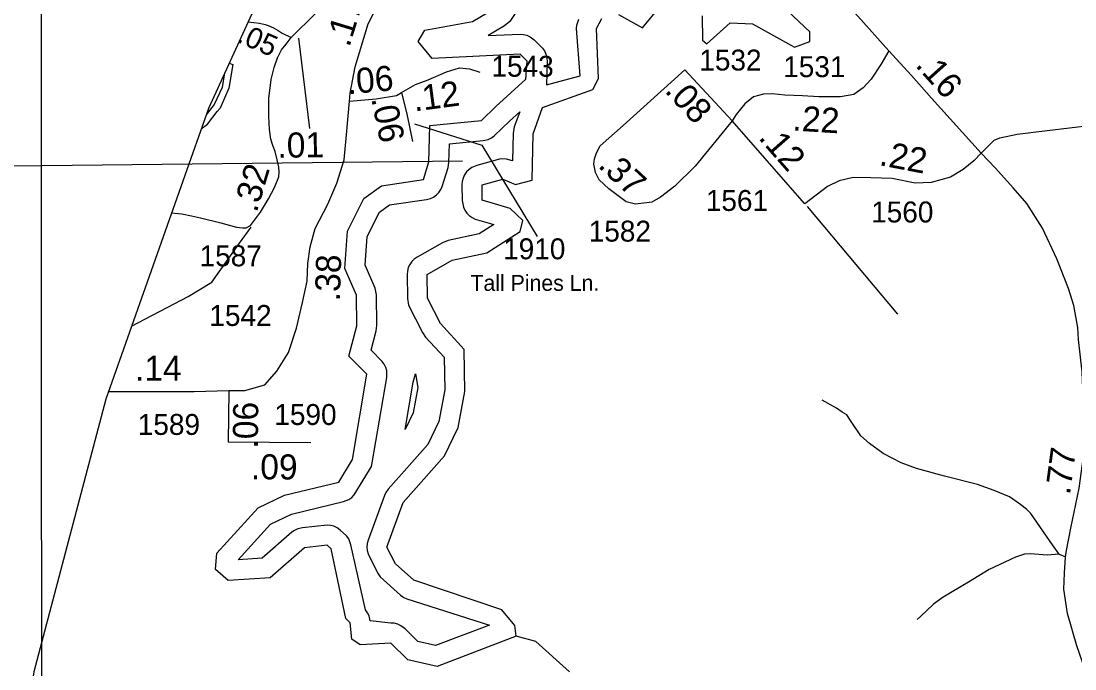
# Model space of a CAD drawing. Extents: x 2290615 to 2522933, y 819489 to 1012715.
# Drawn here: x 2321678 to 2327975, y 999420 to 1003289 of the extents above; entities that cross this region are included whole.
import ezdxf

# ---------------------------------------------------------------- set-up
doc = ezdxf.new("R2010")
doc.units = 0
for name, color, linetype in [('Exist Boundary Political CountyLine', 7, 'Continuous'), ('Exist Hydrographic Buffer Line', 7, 'Continuous'), ('Exist Hydrographic Creek Single Shore', 7, 'Continuous'), ('Exist Hydrographic Lake Shore', 7, 'Continuous'), ('Exist Road Non-System Type 51', 7, 'Continuous'), ('Exist Road Secondary Mileage Tenths English Label', 7, 'Continuous'), ('Exist Road Secondary Type 51 Attributed', 7, 'Continuous'), ('Exist Road Secondary Type 51 Label', 7, 'Continuous'), ('Exist Road Secondary Type 51 Number Label', 7, 'Continuous'), ('Map Preparation Inset Cut Line', 7, 'Continuous'), ('Map Preparation Longitude Latitude Lines', 7, 'Continuous')]:
    doc.layers.add(name, color=color, linetype=linetype)

msp = doc.modelspace()

# ---------------------------------------------------------------- linework, layer by layer
at = {"layer": 'Exist Boundary Political CountyLine'}
msp.add_lwpolyline([(2323478.1, 1004252.3), (2322797.9, 1002767.9), (2322184.3, 1001030.3), (2321753.9, 999403.1), (2320741.4, 993201.9), (2320116, 981859.9), (2320039, 981847.1), (2319958.9, 981832.4), (2319871.3, 981814.3), (2319737.2, 981784.5), (2319631.4, 981753.5), (2319582.3, 981738.9), (2319462.8, 981696.8)], dxfattribs=at)
at = {"layer": 'Exist Hydrographic Buffer Line'}
for points in [[(2324705.6, 1003451.2), (2324598.8, 1003287.4), (2324567.8, 1003261.1), (2324468.6, 1003202.8), (2324659.7, 1003211.8), (2324680.6, 1003209.9), (2324700.7, 1003204.5), (2324719.8, 1003195.7), (2324743.5, 1003177.7), (2324793.8, 1003128), (2324805.7, 1003110.9), (2324814.5, 1003091.9), (2324820, 1003071.7), (2324821.5, 1003043.2), (2324817.8, 1002908.1), (2324982, 1002951.9), (2325019.3, 1002961.8), (2324996.8, 1003245.2), (2324998.4, 1003266)], [(2324998.4, 1003266), (2325010.7, 1003301.4)], [(2322894.8, 1002979.5), (2322879.1, 1002893.5), (2322832, 1002791.2), (2322784.3, 1002729.5)], [(2324154.6, 999559.2), (2324048.8, 999582.6), (2323972.6, 999658.7), (2323947.7, 999677.8), (2323928.9, 999686.6), (2323908.6, 999692.1), (2323887.9, 999693.8), (2323764.4, 999706.1), (2323757.7, 999736.3), (2323748.8, 999755.1), (2323736.7, 999772.2), (2323649.4, 1000161.4), (2323635.9, 1000197), (2323623.8, 1000214.1), (2323585.8, 1000249.2), (2323566.8, 1000262.8), (2323547.9, 1000271.6), (2323527.6, 1000277.1), (2323506.9, 1000278.8), (2323359.2, 1000262.8), (2323331.8, 1000256.3), (2323312.9, 1000247.4), (2323295.7, 1000235.5), (2323118.5, 1000081.3), (2322974.6, 1000071.6), (2323168.5, 1000283.4), (2323293.6, 1000343.3), (2323605.3, 1000419.4), (2323636.9, 1000432), (2323654.1, 1000444), (2323668.9, 1000458.9), (2323761.3, 1000608.3), (2323771.6, 1000629.6), (2323777.1, 1000649.9), (2323863.1, 1001159.7), (2323864.9, 1001179.7), (2323863.1, 1001200.5), (2323857.5, 1001220.8), (2323848.9, 1001239.7), (2323836.8, 1001256.8), (2323769.5, 1001323.7), (2323799.9, 1001438.9), (2323803.8, 1001470.7), (2323801.7, 1001654.4), (2323794.6, 1001694.1), (2323735.3, 1001832.2), (2323746, 1002002.9), (2323819.6, 1002149), (2323879, 1002191.5), (2324100.1, 1002223.8), (2324123.9, 1002229.8), (2324142.7, 1002238.6), (2324160, 1002250.6), (2324174.7, 1002265.5), (2324186.8, 1002282.6), (2324195.4, 1002301.5), (2324229.7, 1002414.4), (2324234.8, 1002445.7), (2324237.7, 1002556.3), (2324440.1, 1002575.6), (2324469.8, 1002582.3), (2324488.9, 1002591.1), (2324506.1, 1002603.1), (2324597.8, 1002692.5), (2324657.8, 1002746.8), (2324625, 1002656.8), (2324617.8, 1002618), (2324615, 1002455.4), (2324578.5, 1002464), (2324557.8, 1002465.8), (2324537.1, 1002464), (2324400.7, 1002426.7), (2324372.8, 1002415.1), (2324355.6, 1002403.1), (2324340.8, 1002388.2), (2324328.7, 1002371.1), (2324320.1, 1002352.1), (2324314.6, 1002331.9), (2324312.7, 1002311.1), (2324313.8, 1002217.9), (2324321.1, 1002178.1), (2324329.8, 1002159.1), (2324341.8, 1002142), (2324356.6, 1002127.3), (2324373.8, 1002115.3), (2324392.7, 1002106.4), (2324503.6, 1002073.7), (2324415.5, 1002018), (2324229.5, 1001977.9), (2324195.6, 1001965), (2324045.5, 1001880), (2324027.5, 1001867.5), (2324012.7, 1001852.7), (2324000.8, 1001835.6), (2323992, 1001816.6), (2323986.5, 1001796.4), (2323984.9, 1001775.6), (2323986.7, 1001632.8), (2323994.1, 1001593.4), (2324076.7, 1001429)], [(2324076.7, 1001429), (2324095.6, 1001402.1), (2324207.3, 1001281), (2324209.6, 1001086.1), (2324174.7, 1000898.5), (2324108.1, 1000760.4), (2323871.9, 1000493.5), (2323857.7, 1000473.9), (2323849.1, 1000455.1), (2323752.1, 1000188.4), (2323746.6, 1000168.2)], [(2323973.2, 1000849.9), (2324020.7, 1001133.1), (2324035.3, 1001181.6), (2324049.6, 1001099.9), (2324021.4, 1000948.8), (2323973.2, 1000849.9)], [(2323746.6, 1000168.2), (2323744.7, 1000147.4), (2323746.6, 1000126.6), (2323752.1, 1000106.3), (2323809.1, 999993.1), (2323823.9, 999970.6), (2323944.9, 999860.9), (2323964.8, 999846.6), (2323983.8, 999837.8), (2324476.4, 999681.8), (2324154.6, 999559.2)]]:
    msp.add_lwpolyline(points, dxfattribs=at)
at = {"layer": 'Exist Hydrographic Creek Single Shore'}
msp.add_lwpolyline([(2324955.8, 999401.2), (2324753.8, 999583.3), (2324636.9, 999614.6)], dxfattribs=at)
at = {"layer": 'Exist Hydrographic Lake Shore'}
for points in [[(2325748.7, 1003320.6), (2325750.8, 1003176.1), (2325775.8, 1003154.3), (2325915.8, 1003278.2), (2326048.7, 1003273.8), (2326300.7, 1003133.2), (2326391.8, 1003166.6), (2326390.7, 1003225.6), (2326121.7, 1003480.3)], [(2325248.8, 1003329.5), (2325390.7, 1003250), (2325497.7, 1003375.8)], [(2324515.5, 1002779.8), (2324694.7, 1002942.2), (2324701.7, 1003050.9), (2324659.7, 1003091.7), (2324134.7, 1003066.9), (2324050.7, 1003168.5), (2324091.7, 1003235.8), (2324374.9, 1003286.7), (2324506.7, 1003364.5)], [(2324794.8, 1002772.4), (2325094.8, 1002880), (2325127.8, 1002947.1), (2325116.7, 1003245.2), (2325148.7, 1003305.6)], [(2322921.7, 1003038.2), (2322943.8, 1003031), (2322920.8, 1002888.7), (2322868.8, 1002769.8)], [(2322754.5, 1002645.1), (2322792.1, 1002674.4), (2322849.7, 1002749), (2322868.8, 1002769.8)], [(2322840.9, 1000013.3), (2322848.9, 1000112), (2323095.7, 1000381.5), (2323252.8, 1000457), (2323576.8, 1000536), (2323658.8, 1000670.7), (2323744.7, 1001179.7), (2323635.9, 1001286.9), (2323683.8, 1001469.4), (2323681.8, 1001653.1), (2323613.7, 1001811.1), (2323627.9, 1002035), (2323725.9, 1002229.4), (2323832.7, 1002306), (2324082.9, 1002342.6), (2324114.9, 1002449), (2324120.8, 1002665.7), (2324428.8, 1002695.1), (2324515.5, 1002779.8)], [(2324636.9, 999614.6), (2324627.9, 999679.9), (2324551.8, 999771.9), (2324024.8, 999950.4), (2323915.8, 1000047.7), (2323864.9, 1000147.4), (2323961.9, 1000413.9), (2324208.8, 1000693.2), (2324289.8, 1000860.8), (2324329.8, 1001075.8), (2324326.9, 1001328.5), (2324183.8, 1001483.5), (2324106.9, 1001634.5), (2324104.8, 1001775.6), (2324254.7, 1001860.6), (2324461.8, 1001905.2), (2324660.7, 1002031.6), (2324676.7, 1002097.8), (2324600.8, 1002170.2), (2324433.7, 1002219.2), (2324432.7, 1002311.1), (2324557.8, 1002345.7), (2324632.8, 1002312.7), (2324732.9, 1002339.8), (2324737.8, 1002615.8), (2324794.8, 1002772.4)], [(2324636.9, 999614.6), (2324163.9, 999434.2), (2323988.7, 999473), (2323887.9, 999573.8), (2323703.9, 999563), (2323653.9, 999597), (2323644.9, 999695.1), (2323618.8, 999720.4), (2323531.9, 1000136.9), (2323506.9, 1000158.9), (2323372.8, 1000143.5), (2323166.9, 999964.3), (2322916.7, 999947.5), (2322840.9, 1000013.3)]]:
    msp.add_lwpolyline(points, dxfattribs=at)
at = {"layer": 'Exist Road Non-System Type 51'}
for p, q in [((2326375, 1002182.6), (2326915.8, 1001538.5)), ((2326375, 1002182.6), (2326915.8, 1001538.5)), ((2327880.9, 1000105.4), (2327919.2, 1000090)), ((2327880.9, 1000105.4), (2327919.2, 1000090))]:
    msp.add_line(p, q, dxfattribs=at)
for points in [[(2327414.5, 1002499.6), (2327454, 1002537.7), (2327493.4, 1002578.7), (2327525.9, 1002592.7), (2327629.7, 1002614.4), (2327809.5, 1002636.1), (2328076, 1002668.7), (2328248, 1002705.9), (2328290.1, 1002715)], [(2322338.5, 1001466.9), (2322676.7, 1001643.7), (2322818, 1001729.7), (2322983.9, 1001963.4), (2323052.7, 1002057.8)], [(2327880.9, 1000105.4), (2327840.9, 1000161.6), (2327712.3, 1000347.7), (2327685.9, 1000374.4), (2327651.7, 1000400.6), (2327624.2, 1000419), (2327585.2, 1000447), (2327493.8, 1000485.7), (2327393.1, 1000521.4), (2327196.3, 1000571), (2327028.9, 1000617.5), (2326937.5, 1000650.1), (2326830.6, 1000705.9), (2326748.4, 1000766.4), (2326696.6, 1000812.3), (2326639.3, 1000897.6), (2326612.9, 1000936.4), (2326585, 1000953.4), (2326550.9, 1000976.7), (2326464.2, 1001024.8)], [(2327880.9, 1000105.4), (2327810.4, 1000098.6), (2327708.1, 1000106.4), (2327674, 1000104.8), (2327621.3, 1000087.8), (2327463.3, 1000013.3), (2327339.3, 999937.4), (2327189, 999847.4), (2327130.1, 999807.1), (2327052.6, 999732.7), (2327032.5, 999714.1)]]:
    msp.add_lwpolyline(points, dxfattribs=at)
at = {"layer": 'Exist Road Secondary Mileage Tenths English Label'}
msp.add_line((2323335.6, 1003186.9), (2323401.7, 1002647.3), dxfattribs=at)
at = {"layer": 'Exist Road Secondary Type 51 Attributed'}
for points in [[(2326864.1, 1003112.6), (2326678.5, 1003319.5), (2326521.6, 1003493), (2326437.5, 1003586.8), (2326392, 1003633.7), (2326368.6, 1003658.5), (2326353.4, 1003680.6), (2326348.4, 1003688.8), (2326341.7, 1003706)], [(2323640.1, 1002810.6), (2323644.1, 1002858.4), (2323674, 1003016.5), (2323752.4, 1003273.2), (2323839.9, 1003445.2), (2323898.4, 1003612.4)], [(2323292.2, 1003190.5), (2323437.5, 1003334.9)], [(2323034.9, 1003285.2), (2323102.7, 1003276.4), (2323136.2, 1003268.7), (2323154.3, 1003263.5), (2323187.2, 1003249.1), (2323214.6, 1003233.4), (2323238.5, 1003217.1), (2323292.2, 1003190.5)], [(2322577.9, 1002144.9), (2322639.5, 1002137.8), (2322696.3, 1002126.5), (2322749.7, 1002115.1), (2322871.7, 1002084.1), (2322966.3, 1002058.5), (2323001.1, 1002053.8), (2323023.4, 1002054.7), (2323049.7, 1002067.4), (2323108.2, 1002148.3), (2323156.9, 1002227.3), (2323192.3, 1002295.1), (2323218.3, 1002358.7), (2323221.3, 1002387.3), (2323219.3, 1002416.5), (2323209.6, 1002461.4), (2323196.2, 1002511), (2323182.9, 1002545.4), (2323171.4, 1002583.6), (2323161.9, 1002642.8), (2323158.1, 1002721.2), (2323158.1, 1002826.2), (2323173.3, 1002940.8), (2323190.5, 1003011.5), (2323210.5, 1003070.8), (2323234.3, 1003117.4), (2323262.7, 1003152.5), (2323292.2, 1003190.5)], [(2326864.1, 1003112.6), (2326815, 1003030.1), (2326757.6, 1002943.2), (2326711.1, 1002890.5), (2326653.8, 1002851.8), (2326574.8, 1002837.8), (2326446.2, 1002836.2), (2326347, 1002842.5), (2326241.6, 1002847.1), (2326165.7, 1002854.9), (2326114.6, 1002853.3), (2326055.7, 1002836.2), (2326003, 1002795.9), (2325951.8, 1002730.8), (2325926.7, 1002693.5)], [(2327414.5, 1002499.6), (2327119.4, 1002828.5), (2326998.1, 1002964.7), (2326864.1, 1003112.6)], [(2323952.3, 1002862.7), (2324034.3, 1002910.2), (2324110, 1002938.1), (2324219.5, 1002985.9), (2324299.1, 1003009.8), (2324356.9, 1003003.8), (2324420.6, 1002983.9)], [(2325190.1, 1002288.1), (2325132.6, 1002341.4), (2325110.8, 1002385), (2325101.5, 1002434.9), (2325104.6, 1002466), (2325117.1, 1002503.4), (2325138.9, 1002543.9), (2325275.9, 1002665.5), (2325643.8, 1002998.4)], [(2325926.7, 1002693.5), (2325643.8, 1002998.4)], [(2322919.3, 1001083.5), (2323015.8, 1001082.8), (2323134.5, 1001117.2), (2323206.9, 1001198.7), (2323276.3, 1001310.5), (2323324.6, 1001455.4), (2323360.8, 1001609.3), (2323387.9, 1001736.1), (2323391, 1001841.8), (2323406, 1001941.4), (2323436.2, 1002050.1), (2323511.6, 1002195), (2323565.9, 1002321.8), (2323608.2, 1002460.7), (2323622.7, 1002609), (2323640.1, 1002810.6)], [(2323640.1, 1002810.6), (2323799.4, 1002824.6), (2323920.9, 1002844.5), (2323952.3, 1002862.7)], [(2323952.3, 1002862.7), (2323984.6, 1002725), (2324016.4, 1002569.6)], [(2325926.7, 1002693.5), (2325705.6, 1002422.4), (2325584.2, 1002304), (2325500.1, 1002238.5), (2325447.1, 1002207.4), (2325416, 1002204.3), (2325350.6, 1002194.9), (2325294.6, 1002210.5), (2325190.1, 1002288.1)], [(2326361.8, 1002197.7), (2325926.7, 1002693.5)], [(2327414.5, 1002499.6), (2327371.9, 1002453.7), (2327306.8, 1002402.5), (2327232.4, 1002357.6), (2327116.2, 1002325), (2327021.7, 1002321.9), (2326883.8, 1002348.3), (2326756.7, 1002352.9), (2326651.3, 1002354.5), (2326567.7, 1002335.9), (2326496.4, 1002301.7), (2326361.8, 1002197.7)], [(2328298.3, 998672.3), (2328214.1, 998885.3), (2328104.6, 999218.2), (2327987, 999556.7), (2327930.8, 999750.1), (2327909.1, 999895.8), (2327912.2, 999991.8), (2327919.2, 1000090), (2327924.7, 1000126), (2327951.4, 1000260.2), (2328000.8, 1000498.7), (2328032.1, 1000732.9), (2328027.4, 1000998.9), (2328019.3, 1001194.6), (2327997.2, 1001386.4), (2327992.4, 1001458.2), (2327969, 1001589.9), (2327938, 1001691.5), (2327868.1, 1001868.7), (2327782.1, 1002051.9), (2327688.5, 1002200.7), (2327607.4, 1002293.8), (2327500.3, 1002410.6), (2327414.5, 1002499.6)], [(2322200.4, 1001075.8), (2322712.3, 1001076), (2322919.3, 1001083.5)], [(2322919.3, 1001083.5), (2322916.6, 1000775.8)], [(2322916.6, 1000775.8), (2323410.5, 1000772.3)]]:
    msp.add_lwpolyline(points, dxfattribs=at)
at = {"layer": 'Exist Road Secondary Type 51 Number Label'}
msp.add_lwpolyline([(2324029.4, 1002674.8), (2324431.4, 1002548.2), (2324761.8, 1002003.1)], dxfattribs=at)
at = {"layer": 'Map Preparation Inset Cut Line'}
msp.add_lwpolyline([(2356768.7, 983323.8), (2328294.4, 983323.8), (2321803.3, 997760.3), (2321797.8, 1007474.2), (2338139.7, 1007474.2), (2356768.7, 1000715)], close=True, dxfattribs=at)
at = {"layer": 'Map Preparation Longitude Latitude Lines'}
msp.add_lwpolyline([(2316039, 1002363.6), (2318751.6, 1002392), (2324316.8, 1002455.1)], dxfattribs=at)

# ---------------------------------------------------------------- texts
at = {"layer": 'Exist Road Secondary Mileage Tenths English Label'}
for s, height, rotation, p in [('.17', 150, 73.00289, (2323639.7, 1003129)), ('.05', 125, 336.24787, (2322962.5, 1003167.2)), ('.06', 150, 5.00273, (2323631, 1002852.1)), ('.16', 150, 311.90159, (2327017.6, 1003023)), ('.12', 150, 7.59809, (2324029.4, 1002749.2)), ('.08', 150, 312.85821, (2325519.5, 1002868.9)), ('.06', 150, 281.58716, (2323769.9, 1002826.8)), ('.22', 150, 356.4208, (2326285.4, 1002636.1)), ('.01', 150, 0.79554, (2323211.1, 1002472.6)), ('.12', 150, 311.26616, (2326079.9, 1002589.9)), ('.22', 150, 349.17883, (2326801.1, 1002429.6)), ('.32', 150, 73.31045, (2323086.2, 1002141)), ('.37', 150, 317.18193, (2325120.8, 1002420.8)), ('.38', 150, 88.36424, (2323583.8, 1001614.7)), ('.14', 150, 0.02773, (2322359.3, 1001140.9)), ('.06', 150, 89.48937, (2323093.4, 1000735.5)), ('.77', 150, 82.38722, (2327945.4, 1000455.1)), ('.09', 150, 359.58589, (2323051.3, 1000552.7))]:
    msp.add_text(s, height=height, rotation=rotation, dxfattribs=at).set_placement(p)
at = {"layer": 'Exist Road Secondary Type 51 Label'}
msp.add_text('Tall Pines Ln.', height=95, rotation=0.02538, dxfattribs=at).set_placement((2324363.7, 1001677.8))
at = {"layer": 'Exist Road Secondary Type 51 Number Label'}
for s, p in [('1532', (2325731.1, 1002994.2)), ('1543', (2324489.1, 1002957)), ('1531', (2326232.4, 1002954.6)), ('1561', (2325769.9, 1002155.4)), ('1560', (2326757.8, 1002086.6)), ('1582', (2325070.3, 1001972.2)), ('1910', (2324558.9, 1001866.6)), ('1587', (2322745.2, 1001824.7)), ('1542', (2322803.5, 1001468.4)), ('1590', (2323191.7, 1000876.7)), ('1589', (2322375.8, 1000817.5))]:
    msp.add_text(s, height=125, dxfattribs=at).set_placement(p)

doc.saveas('drawing.dxf')
